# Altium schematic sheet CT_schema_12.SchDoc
size 278 x 170 mm
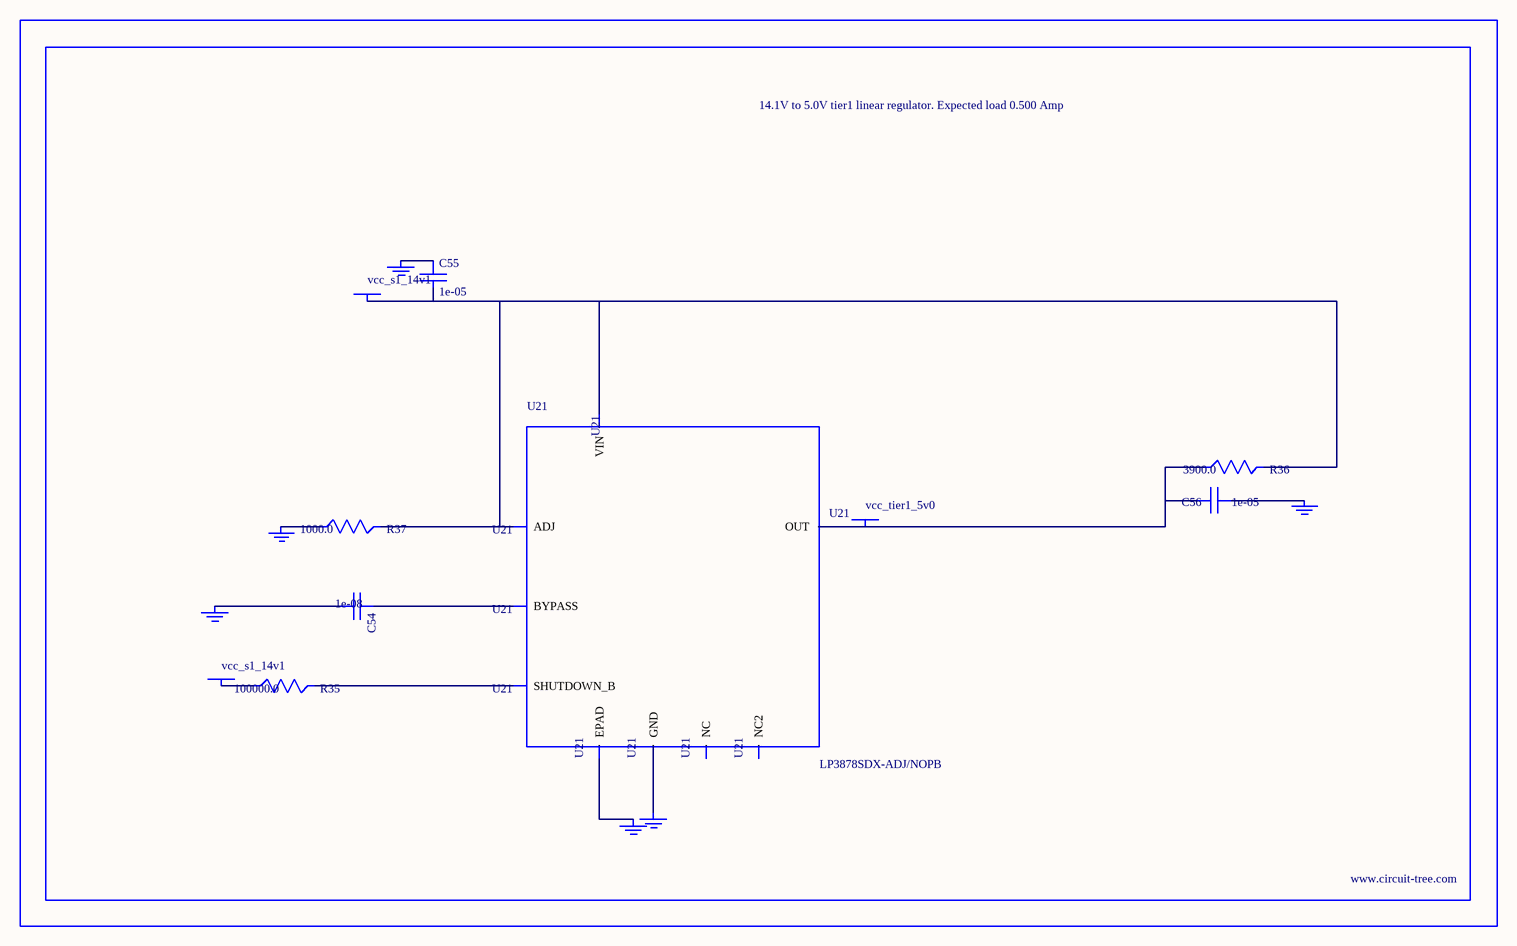
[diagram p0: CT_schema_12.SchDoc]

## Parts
BORDER11  (no value)
C54  1e-08  [C0402]
C55  1e-05  [C1210]
C56  1e-05  [C1210]
GND_INSTANCE_11_0  (no value)
GND_INSTANCE_11_1  (no value)
GND_INSTANCE_11_2  (no value)
GND_INSTANCE_11_3  (no value)
GND_INSTANCE_11_4  (no value)
GND_INSTANCE_11_5  (no value)
POWER_INSTANCE_11_0  vcc_s1_14v1
POWER_INSTANCE_11_1  vcc_s1_14v1
POWER_INSTANCE_11_2  vcc_tier1_5v0
R35  100000.0  [R0603]
R36  3900.0  [R0603]
R37  1000.0  [R0603]
U21  LP3878SDX-ADJ/NOPB  [WSON-8]

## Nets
NetC54_1: C54.1 U21.1(BYPASS)
NetC54_2: C54.2 GND_INSTANCE_11_0.0(GND)
NetC55_1: C55.1 GND_INSTANCE_11_1.0(GND)
NetC55_2: C55.2 POWER_INSTANCE_11_0.0(PWR) R36.2 R37.2 U21.4(VIN) U21.6(ADJ)
NetC56_1: C56.1 GND_INSTANCE_11_2.0(GND)
NetC56_2: C56.2 POWER_INSTANCE_11_2.0(PWR) R36.1 U21.5(OUT)
NetGND_INSTANCE_11_3_0: GND_INSTANCE_11_3.0(GND) R37.1
NetGND_INSTANCE_11_4_0: GND_INSTANCE_11_4.0(GND) U21.PAD(EPAD)
NetGND_INSTANCE_11_5_0: GND_INSTANCE_11_5.0(GND) U21.3(GND)
NetPOWER_INSTANCE_11_1_0: POWER_INSTANCE_11_1.0(PWR) R35.1
NetR35_2: R35.2 U21.8(SHUTDOWN_B)

Not connected (* = marked no-connect by the designer): U21 2(NC) 7(NC2)

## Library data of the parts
BORDER11 = BORDER_PAGE11
C54 = C0402C103K3RAC
C55 = C1210C106K5PACTU
C56 = GRM32DR61E106MA12L
GND_INSTANCE_11_0-GND_INSTANCE_11_5 = GND
POWER_INSTANCE_11_0-POWER_INSTANCE_11_2 = PWR
R35 = RC0603JR-07100KL
R36 = RC0603JR-073K9L
R37 = RC0603JR-071KL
